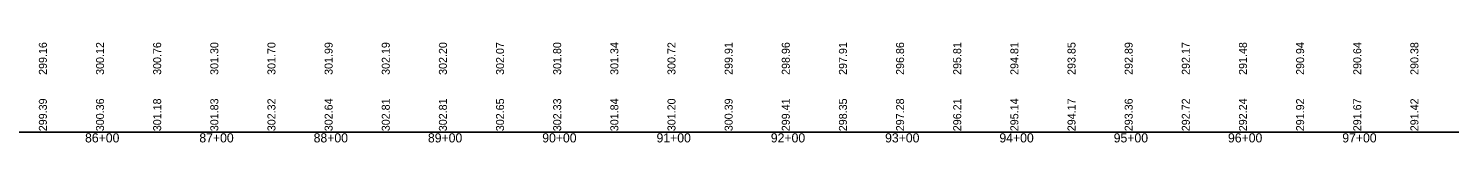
# Model space of a CAD drawing. Extents: x 1876258 to 1932803, y 754739 to 837911.
# Drawn here: x 1886896 to 1888139, y 827954 to 828041 of the extents above; entities that cross this region are included whole.
import ezdxf

# ---------------------------------------------------------------- set-up
doc = ezdxf.new("R2010")
doc.units = 0
for name, color, linetype in [('RD_DDB_StaTX', 7, 'Continuous'), ('RD_DDB_StripGrade', 7, 'Continuous'), ('RD_GPK_Profile_Cell', 7, 'Continuous')]:
    doc.layers.add(name, color=color, linetype=linetype)

msp = doc.modelspace()

# ---------------------------------------------------------------- linework, layer by layer
at = {"layer": 'RD_GPK_Profile_Cell'}
msp.add_line((1878363.1, 827962.8), (1926563.1, 827962.8), dxfattribs=at)

# ---------------------------------------------------------------- texts
at = {"layer": 'RD_DDB_StaTX'}
for s, p in [('86+00', (1886945.5, 827953.8)), ('87+00', (1887045.5, 827953.8)), ('88+00', (1887145.5, 827953.8)), ('89+00', (1887245.5, 827953.8)), ('90+00', (1887345.5, 827953.8)), ('91+00', (1887445.5, 827953.8)), ('92+00', (1887545.5, 827953.8)), ('93+00', (1887645.5, 827953.8)), ('94+00', (1887745.5, 827953.8)), ('95+00', (1887845.5, 827953.8)), ('96+00', (1887945.5, 827953.8)), ('97+00', (1888045.5, 827953.8))]:
    msp.add_text(s, height=8, dxfattribs=at).set_placement(p)
at = {"layer": 'RD_DDB_StripGrade'}
for s, p in [('299.16', (1886912.1, 828012.8)), ('300.12', (1886962.1, 828012.8)), ('300.76', (1887012.1, 828012.8)), ('301.30', (1887062.1, 828012.8)), ('301.70', (1887112.1, 828012.8)), ('301.99', (1887162.1, 828012.8)), ('302.19', (1887212.1, 828012.8)), ('302.20', (1887262.1, 828012.8)), ('302.07', (1887312.1, 828012.8)), ('301.80', (1887362.1, 828012.8)), ('301.34', (1887412.1, 828012.8)), ('300.72', (1887462.1, 828012.8)), ('299.91', (1887512.1, 828012.8)), ('298.96', (1887562.1, 828012.8)), ('297.91', (1887612.1, 828012.8)), ('296.86', (1887662.1, 828012.8)), ('295.81', (1887712.1, 828012.8)), ('294.81', (1887762.1, 828012.8)), ('293.85', (1887812.1, 828012.8)), ('292.89', (1887862.1, 828012.8)), ('292.17', (1887912.1, 828012.8)), ('291.48', (1887962.1, 828012.8)), ('290.94', (1888012.1, 828012.8)), ('290.64', (1888062.1, 828012.8)), ('290.38', (1888112.1, 828012.8)), ('299.39', (1886912.1, 827963.6)), ('300.36', (1886962.1, 827963.6)), ('301.18', (1887012.1, 827963.6)), ('301.83', (1887062.1, 827963.6)), ('302.32', (1887112.1, 827963.6)), ('302.64', (1887162.1, 827963.6)), ('302.81', (1887212.1, 827963.6)), ('302.81', (1887262.1, 827963.6)), ('302.65', (1887312.1, 827963.6)), ('302.33', (1887362.1, 827963.6)), ('301.84', (1887412.1, 827963.6)), ('301.20', (1887462.1, 827963.6)), ('300.39', (1887512.1, 827963.6)), ('299.41', (1887562.1, 827963.6)), ('298.35', (1887612.1, 827963.6)), ('297.28', (1887662.1, 827963.6)), ('296.21', (1887712.1, 827963.6)), ('295.14', (1887762.1, 827963.6)), ('294.17', (1887812.1, 827963.6)), ('293.36', (1887862.1, 827963.6)), ('292.72', (1887912.1, 827963.6)), ('292.24', (1887962.1, 827963.6)), ('291.92', (1888012.1, 827963.6)), ('291.67', (1888062.1, 827963.6)), ('291.42', (1888112.1, 827963.6))]:
    msp.add_text(s, height=7, rotation=90, dxfattribs=at).set_placement(p)

doc.saveas('drawing.dxf')
